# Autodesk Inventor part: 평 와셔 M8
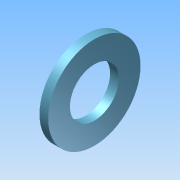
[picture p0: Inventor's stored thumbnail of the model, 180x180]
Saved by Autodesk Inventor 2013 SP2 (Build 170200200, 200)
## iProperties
Created: 2025-10
Part Number: 평 와셔 M8
Material: Generic
Document SubType Name: Modeling
Designer: 601
Density: 1 g/cm^3
Author: 601
변환 표준: STEP AP214IS
전처리기: Build: 200, Release: 2013 SP2 Update 6 - Date: Thu 07/17/2014
전송 단위: 밀리미터
불확실성: 0.01
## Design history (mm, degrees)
node "평 와셔 M81"
body "Solid1"
node "기준1"
